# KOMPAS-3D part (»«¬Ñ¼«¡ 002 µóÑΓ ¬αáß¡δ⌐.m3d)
File: created 22.07.2016 16:41:15, last saved 22.07.2016 16:58:16.
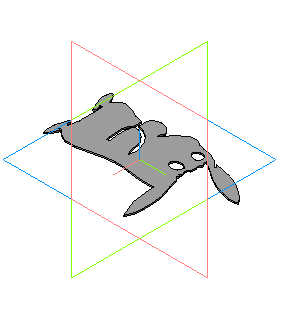
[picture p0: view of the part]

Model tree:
1. Эскиз:1
2. Операция выдавливания:1
     Расстояние 1 = 0.5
